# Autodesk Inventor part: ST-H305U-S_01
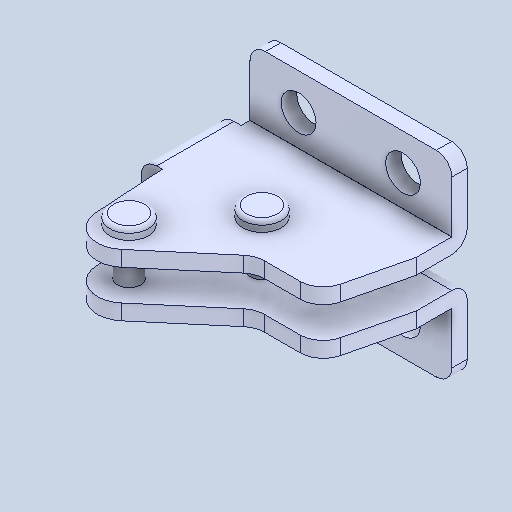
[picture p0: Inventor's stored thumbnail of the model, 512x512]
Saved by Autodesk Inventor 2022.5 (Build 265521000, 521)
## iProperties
Created: 2024-07
Part Number: ST-H305U-S_01
Material: 一般
Document SubType Name: Modeling
Designer: ImaoCorp
Density: 1 g/cm^3
Appearance: 既定
Author: ImaoCorp
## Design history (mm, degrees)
feature "ST-H305U-S_01"
node "ソリッド1"
